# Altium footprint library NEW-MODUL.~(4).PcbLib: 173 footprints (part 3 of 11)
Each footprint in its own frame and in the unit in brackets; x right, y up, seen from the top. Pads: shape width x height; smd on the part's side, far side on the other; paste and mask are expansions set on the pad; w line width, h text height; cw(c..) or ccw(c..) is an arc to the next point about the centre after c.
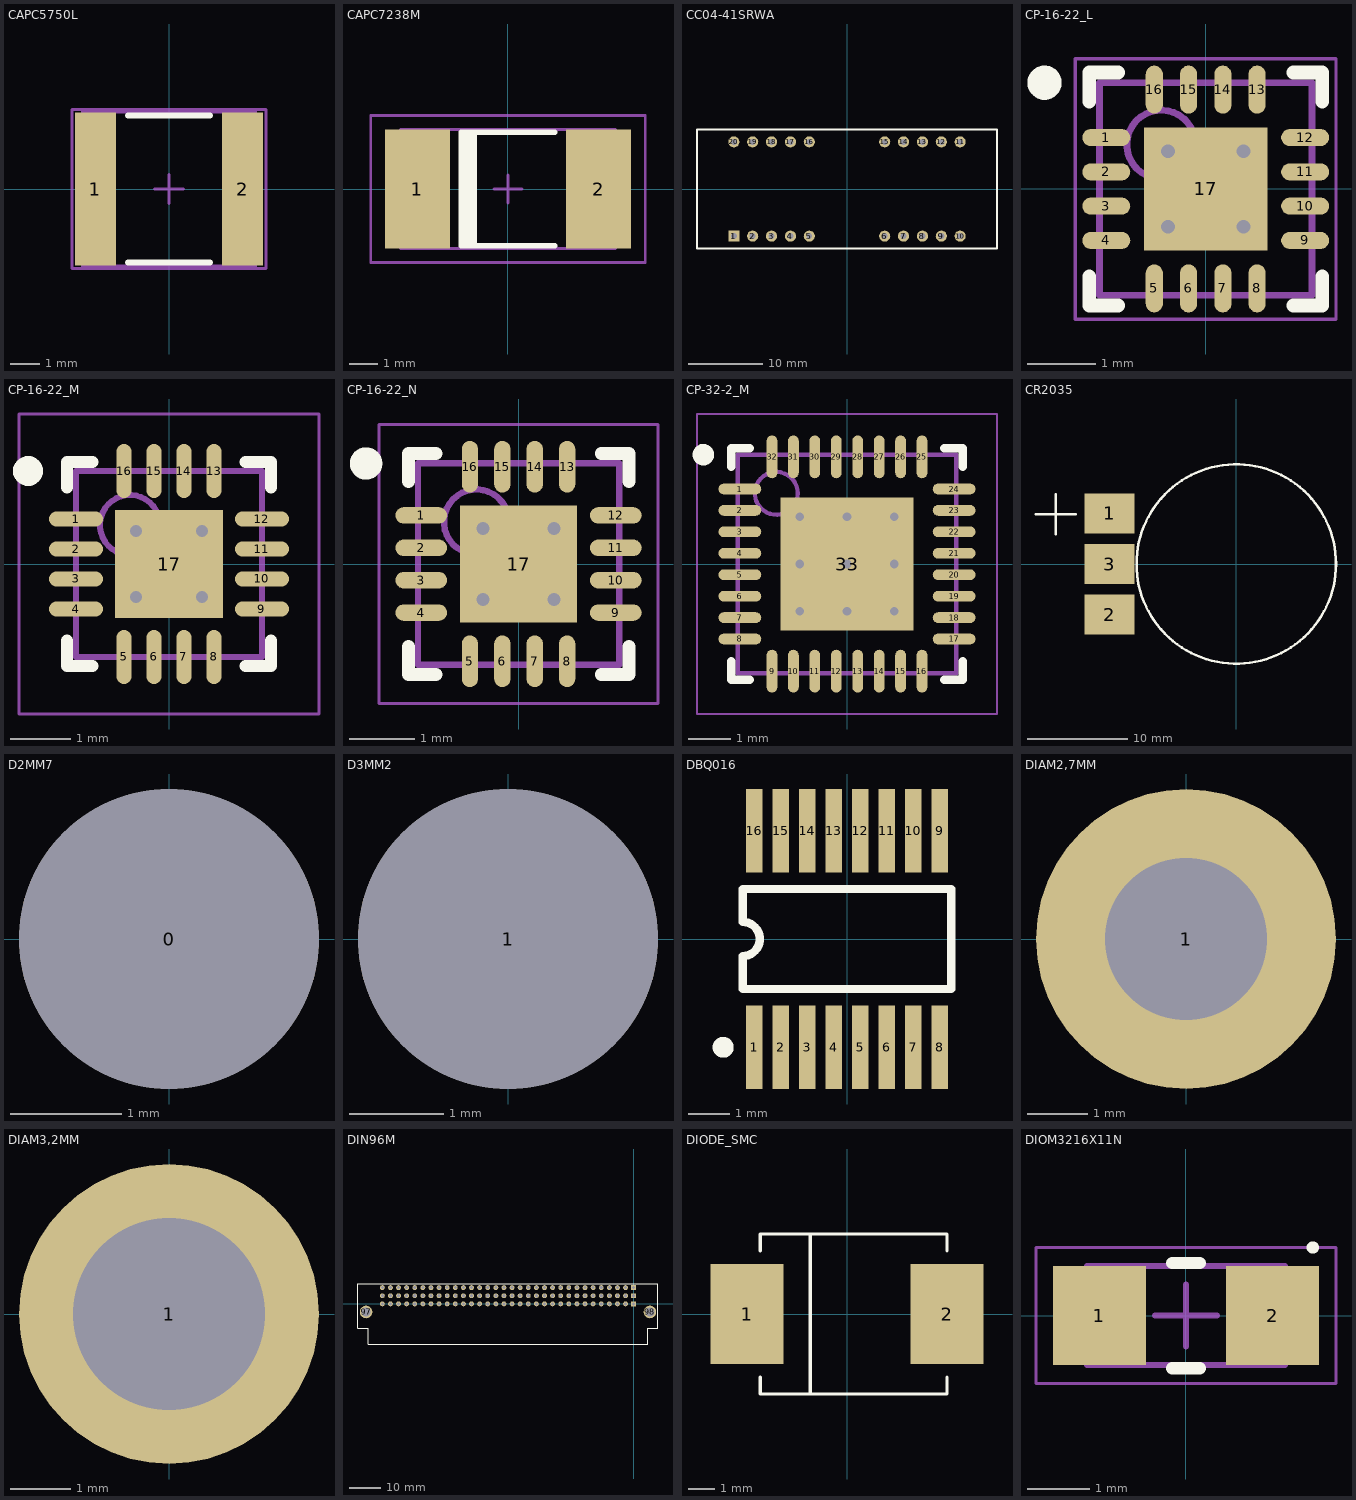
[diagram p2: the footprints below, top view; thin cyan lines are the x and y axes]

## CAPC5750L [mm] "Chip Capacitor, Body 5.7x5.0mm, IPC High Density"
height 1.35
pads (2):
  rect 1.4x5.2 smd: 1(-2.5,0) 2(2.5,0)
Top Overlay:
  lines w0.2: -1.4,-2.5 1.4,-2.5 ; -1.4,2.5 1.4,2.5
Mechanical 13:
  lines w0.1: -2.95,-2.625 2.95,-2.625 2.95,2.625 -2.95,2.625 -2.95,-2.625
Mechanical 15:
  lines w0.1: -0.5,0 0.5,0 ; 0,-0.5 0,0.5 ; -3.3,-2.7 3.3,-2.7 3.3,2.7 -3.3,2.7 -3.3,-2.7
3D body "User Library-CAPC5750X23.step": height 2.3, standoff 0, extent -2.85,-2.5 2.85,2.5

## CAPC7238M [mm] "Chip Capacitor, Body 7.2x3.8mm, IPC Low Density"
height 3.18
pads (2):
  rect 2.3x4.2 smd: 1(-3.2,0) 2(3.2,0)
Top Overlay:
  rectangle: -1.65,-2 -1.1,2
  lines w0.2: 1.65,-2 -1.65,-2 -1.65,2 1.65,2
Mechanical 13:
  lines w0.1: -3.8,-2.1 3.8,-2.1 3.8,2.1 -3.8,2.1 -3.8,-2.1
Mechanical 15:
  lines w0.1: -0.5,0 0.5,0 ; 0,-0.5 0,0.5 ; -4.85,-2.6 4.85,-2.6 4.85,2.6 -4.85,2.6 -4.85,-2.6
3D body "User Library-CAP_TANT_7343-31.step": height 3.1, standoff 0, extent -3.8,-2.3 3.8,2.3

## CC04-41SRWA [mm]
pads (20):
  rect 1.5x1.5 hole 0.8: 1(-15.24,-6.35)
  round 1.5 hole 0.8: 2(-12.7,-6.35) 3(-10.16,-6.35) 4(-7.62,-6.35) 5(-5.08,-6.35) 6(5.08,-6.35) 7(7.62,-6.35) 8(10.16,-6.35) 9(12.7,-6.35) 10(15.24,-6.35) 11(15.24,6.35) 12(12.7,6.35) 13(10.16,6.35) 14(7.62,6.35) 15(5.08,6.35) 16(-5.08,6.35) 17(-7.62,6.35) 18(-10.16,6.35) 19(-12.7,6.35) 20(-15.24,6.35)
Top Overlay:
  lines w0.254: -20.2,-8 -20.2,8 20.2,8 20.2,-8 -20.2,-8
3D body "end-el-san Co Ltd-King Bright CA04-41.step": height 7, standoff -4, extent -20.2,-8 20.2,8

## CP-16-22_L [mm] "QFN, 16-Leads, Body 3x3mm, Pitch 0.5mm, Thermal Pad 1.75x1.75mm, IPC High Density"
height 0.8
pads (17):
  oval 0.7x0.25 smd: 1(-1.45,0.75) 2(-1.45,0.25) 3(-1.45,-0.25) 4(-1.45,-0.75) 9(1.45,-0.75) 10(1.45,-0.25) 11(1.45,0.25) 12(1.45,0.75)
  oval 0.25x0.7 smd: 5(-0.75,-1.45) 6(-0.25,-1.45) 7(0.25,-1.45) 8(0.75,-1.45) 13(0.75,1.45) 14(0.25,1.45) 15(-0.25,1.45) 16(-0.75,1.45)
  rect 1.8x1.8 smd: 17(0,0)
via -0.55,0.55 diameter 0.5 hole 0.2
via 0.55,0.55 diameter 0.5 hole 0.2
via -0.55,-0.55 diameter 0.5 hole 0.2
via 0.55,-0.55 diameter 0.5 hole 0.2
Top Overlay:
  circle w0.25: c-2.35,1.55 r0.125
  lines w0.2: -1.7,-1.275 -1.7,-1.7 -1.275,-1.7 ; -1.7,1.275 -1.7,1.7 -1.275,1.7 ; 1.275,-1.7 1.7,-1.7 1.7,-1.275 ; 1.275,1.7 1.7,1.7 1.7,1.275
Mechanical 13:
  circle w0.1: c-0.65,0.65 r0.5
  lines w0.1: -1.55,-1.55 -1.55,1.55 1.55,1.55 1.55,-1.55 -1.55,-1.55
Mechanical 15:
  lines w0.05: -1.9,-1.9 -1.9,1.9 1.9,1.9 1.9,-1.9 -1.9,-1.9
  lines w0.1: -0.5,0 0.5,0 ; 0,-0.5 0,0.5
3D body: height 0.8, standoff 0, extent -1.55,-1.55 1.55,1.55

## CP-16-22_M [mm] "QFN, 16-Leads, Body 3x3mm, Pitch 0.5mm, Thermal Pad 1.75x1.75mm, IPC Low Density"
height 0.8
pads (17):
  oval 0.9x0.25 smd: 1(-1.55,0.75) 2(-1.55,0.25) 3(-1.55,-0.25) 4(-1.55,-0.75) 9(1.55,-0.75) 10(1.55,-0.25) 11(1.55,0.25) 12(1.55,0.75)
  oval 0.25x0.9 smd: 5(-0.75,-1.55) 6(-0.25,-1.55) 7(0.25,-1.55) 8(0.75,-1.55) 13(0.75,1.55) 14(0.25,1.55) 15(-0.25,1.55) 16(-0.75,1.55)
  rect 1.8x1.8 smd: 17(0,0)
via -0.55,0.55 diameter 0.5 hole 0.2
via 0.55,0.55 diameter 0.5 hole 0.2
via -0.55,-0.55 diameter 0.5 hole 0.2
via 0.55,-0.55 diameter 0.5 hole 0.2
Top Overlay:
  circle w0.25: c-2.35,1.55 r0.125
  lines w0.2: -1.7,-1.275 -1.7,-1.7 -1.275,-1.7 ; -1.7,1.275 -1.7,1.7 -1.275,1.7 ; 1.275,-1.7 1.7,-1.7 1.7,-1.275 ; 1.275,1.7 1.7,1.7 1.7,1.275
Mechanical 13:
  circle w0.1: c-0.65,0.65 r0.5
  lines w0.1: -1.55,-1.55 -1.55,1.55 1.55,1.55 1.55,-1.55 -1.55,-1.55
Mechanical 15:
  lines w0.05: -2.5,-2.5 -2.5,2.5 2.5,2.5 2.5,-2.5 -2.5,-2.5
  lines w0.1: -0.5,0 0.5,0 ; 0,-0.5 0,0.5
3D body "User Library-QFN-16.step": height 0.9, standoff 0, extent -1.501,-1.501 1.501,1.501

## CP-16-22_N [mm] "QFN, 16-Leads, Body 3x3mm, Pitch 0.5mm, Thermal Pad 1.75x1.75mm, IPC Medium Density"
height 0.8
pads (17):
  oval 0.8x0.25 smd: 1(-1.5,0.75) 2(-1.5,0.25) 3(-1.5,-0.25) 4(-1.5,-0.75) 9(1.5,-0.75) 10(1.5,-0.25) 11(1.5,0.25) 12(1.5,0.75)
  oval 0.25x0.8 smd: 5(-0.75,-1.5) 6(-0.25,-1.5) 7(0.25,-1.5) 8(0.75,-1.5) 13(0.75,1.5) 14(0.25,1.5) 15(-0.25,1.5) 16(-0.75,1.5)
  rect 1.8x1.8 smd: 17(0,0)
via -0.55,0.55 diameter 0.5 hole 0.2
via 0.55,0.55 diameter 0.5 hole 0.2
via -0.55,-0.55 diameter 0.5 hole 0.2
via 0.55,-0.55 diameter 0.5 hole 0.2
Top Overlay:
  circle w0.25: c-2.35,1.55 r0.125
  lines w0.2: -1.7,-1.275 -1.7,-1.7 -1.275,-1.7 ; -1.7,1.275 -1.7,1.7 -1.275,1.7 ; 1.275,-1.7 1.7,-1.7 1.7,-1.275 ; 1.275,1.7 1.7,1.7 1.7,1.275
Mechanical 13:
  circle w0.1: c-0.65,0.65 r0.5
  lines w0.1: -1.55,-1.55 -1.55,1.55 1.55,1.55 1.55,-1.55 -1.55,-1.55
Mechanical 15:
  lines w0.05: -2.15,-2.15 -2.15,2.15 2.15,2.15 2.15,-2.15 -2.15,-2.15
  lines w0.1: -0.5,0 0.5,0 ; 0,-0.5 0,0.5
3D body: height 0.8, standoff 0, extent -1.55,-1.55 1.55,1.55

## CP-32-2_M [mm] "QFN, 32-Leads, Body 5x5mm, Pitch 0.5mm, Thermal Pad 3.1x3.1mm, IPC Low Density"
height 1
pads (33):
  oval 1x0.25 smd: 1(-2.5,1.75) 2(-2.5,1.25) 3(-2.5,0.75) 4(-2.5,0.25) 5(-2.5,-0.25) 6(-2.5,-0.75) 7(-2.5,-1.25) 8(-2.5,-1.75) 17(2.5,-1.75) 18(2.5,-1.25) 19(2.5,-0.75) 20(2.5,-0.25) 21(2.5,0.25) 22(2.5,0.75) 23(2.5,1.25) 24(2.5,1.75)
  oval 0.25x1 smd: 9(-1.75,-2.5) 10(-1.25,-2.5) 11(-0.75,-2.5) 12(-0.25,-2.5) 13(0.25,-2.5) 14(0.75,-2.5) 15(1.25,-2.5) 16(1.75,-2.5) 25(1.75,2.5) 26(1.25,2.5) 27(0.75,2.5) 28(0.25,2.5) 29(-0.25,2.5) 30(-0.75,2.5) 31(-1.25,2.5) 32(-1.75,2.5)
  rect 3.1x3.1 smd: 33(0,0)
via -1.1,1.1 diameter 0.5 hole 0.2
via 0,1.1 diameter 0.5 hole 0.2
via 1.1,1.1 diameter 0.5 hole 0.2
via -1.1,0 diameter 0.5 hole 0.2
via 0,0 diameter 0.5 hole 0.2
via 1.1,0 diameter 0.5 hole 0.2
via -1.1,-1.1 diameter 0.5 hole 0.2
via 0,-1.1 diameter 0.5 hole 0.2
via 1.1,-1.1 diameter 0.5 hole 0.2
Top Overlay:
  circle w0.25: c-3.35,2.55 r0.125
  lines w0.2: -2.7,-2.275 -2.7,-2.7 -2.275,-2.7 ; -2.7,2.275 -2.7,2.7 -2.275,2.7 ; 2.275,-2.7 2.7,-2.7 2.7,-2.275 ; 2.275,2.7 2.7,2.7 2.7,2.275
Mechanical 13:
  circle w0.1: c-1.65,1.65 r0.5
  lines w0.1: -2.55,-2.55 -2.55,2.55 2.55,2.55 2.55,-2.55 -2.55,-2.55
Mechanical 15:
  lines w0.05: -3.5,-3.5 -3.5,3.5 3.5,3.5 3.5,-3.5 -3.5,-3.5
  lines w0.1: -0.5,0 0.5,0 ; 0,-0.5 0,0.5
3D body "User Library-LFCSP-32.step": height 0.89, standoff -0.04, extent -2.51,-2.51 2.51,2.51

## CR2035 [mm]
pads (3):
  rect 5x4 smd: 1(-12.7,5.08) 2(-12.7,-5.08) 3(-12.7,0)
Top Overlay:
  circle w0.254: c0,0 r10
  lines w0.254: -20.08,5 -16.08,5 ; -18.08,3 -18.08,7
3D body "User Library-cr2032.step": height 3.82, standoff 0.02, extent -15,-9.908 10.008,10.108

## D2MM7 [mm]
pads (1):
  round 2.7 hole 2.7 unplated: 0(0,0)

## D3MM2 [mm]
pads (1):
  round 3.2 hole 3.2 unplated: 1(0,0)

## DBQ016 [mm] "SSOP; 16 Leads; Body Width 3.9 mm; Pitch 0.635 mm"
height 1.76
pads (16):
  rect 0.4x2 smd: 1(-2.222,-2.6) 2(-1.587,-2.6) 3(-0.953,-2.6) 4(-0.318,-2.6) 5(0.318,-2.6) 6(0.953,-2.6) 7(1.587,-2.6) 8(2.222,-2.6) 9(2.222,2.6) 10(1.587,2.6) 11(0.953,2.6) 12(0.318,2.6) 13(-0.318,2.6) 14(-0.953,2.6) 15(-1.587,2.6) 16(-2.222,2.6)
Top Overlay:
  circle w0.25: c-2.973,-2.6 r0.125
  lines w0.2: -2.5,-1.2 -2.5,-0.408 ccw(c-2.5,0) -2.5,0.408 -2.5,1.2 2.5,1.2 2.5,-1.2 -2.5,-1.2
3D body "User Library-IPC SO(1).step": height 1.9, standoff 0, extent -2.5,-3.028 2.5,3.028

## DIAM2,7MM [mm]
pads (1):
  round 5 hole 2.7: 1(0,0)

## DIAM3,2MM [mm]
pads (1):
  round 5 hole 3.2: 1(0,0)

## DIN96M [mil]
pads (98):
  rect 60x60 hole 38: 1(0,0) 33(0,100) 65(0,200)
  round 60 hole 38: 2(-100,0) 3(-200,0) 4(-300,0) 5(-400,0) 6(-500,0) 7(-600,0) 8(-700,0) 9(-800,0) 10(-900,0) 11(-1000,0) 12(-1100,0) 13(-1200,0) 14(-1300,0) 15(-1400,0) 16(-1500,0) 17(-1600,0) 18(-1700,0) 19(-1800,0) 20(-1900,0) 21(-2000,0) 22(-2100,0) 23(-2200,0) 24(-2300,0) 25(-2400,0) 26(-2500,0) 27(-2600,0) 28(-2700,0) 29(-2800,0) 30(-2900,0) 31(-3000,0) 32(-3100,0) 34(-100,100) 35(-200,100) 36(-300,100) 37(-400,100) 38(-500,100) 39(-600,100) 40(-700,100) 41(-800,100) 42(-900,100) 43(-1000,100) 44(-1100,100) 45(-1200,100) 46(-1300,100) 47(-1400,100) 48(-1500,100) 49(-1600,100) 50(-1700,100) 51(-1800,100) 52(-1900,100) 53(-2000,100) 54(-2100,100) 55(-2200,100) 56(-2300,100) 57(-2400,100) 58(-2500,100) 59(-2600,100) 60(-2700,100) 61(-2800,100) 62(-2900,100) 63(-3000,100) 64(-3100,100) 66(-100,200) 67(-200,200) 68(-300,200) 69(-400,200) 70(-500,200) 71(-600,200) 72(-700,200) 73(-800,200) 74(-900,200) 75(-1000,200) 76(-1100,200) 77(-1200,200) 78(-1300,200) 79(-1400,200) 80(-1500,200) 81(-1600,200) 82(-1700,200) 83(-1800,200) 84(-1900,200) 85(-2000,200) 86(-2100,200) 87(-2200,200) 88(-2300,200) 89(-2400,200) 90(-2500,200) 91(-2600,200) 92(-2700,200) 93(-2800,200) 94(-2900,200) 95(-3000,200) 96(-3100,200)
  round 156 hole 110: 97(-3300,-100) 98(200,-100)
Top Overlay:
  lines w10: -3400,-300 -3275,-300 -3275,-500 175,-500 175,-300 300,-300 300,250 -3400,250 -3400,-300
3D body "connector_a-cm96abcr.stp": height 376.58, standoff -117.51, extent -3400.39,-500 300.39,213

## DIODE_SMC [mil]
pads (2):
  rect 110x150 smd: 1(-150,0) 2(150,0)
Top Overlay:
  lines w5: -130,-95 -130,-120 150,-120 150,-95 ; -130,95 -130,120 150,120 150,95 ; -55,-120 -55,120
Mechanical 1:
  lines w1: -130,-120 150,-120 ; -130,120 150,120
3D body "User Library-Diode Molded Body.step": height 85.64, standoff 0.6, extent -155.51,-118.11 155.51,118.11

## DIOM3216X11N [mm] "Molded Diode, 2-Leads, Body 3,20x1,60mm, IPC Medium Density"
height 1.1
pads (2):
  rect 1.5x1.6 smd: 1(-1.4,0) 2(1.4,0)
Top Overlay:
  circle w0.1: c2.05,1.1 r0.05
  lines w0.2: -0.225,-0.85 0.225,-0.85 ; -0.225,0.85 0.225,0.85
Mechanical 13:
  rectangle: 1.17,-0.8 1.6,0.8
  lines w0.1: -1.6,-0.8 1.6,-0.8 1.6,0.8 -1.6,0.8 -1.6,-0.8
Mechanical 15:
  lines w0.05: -2.425,-1.1 2.425,-1.1 2.425,1.1 -2.425,1.1 -2.425,-1.1
  lines w0.1: -0.5,0 0.5,0 ; 0,-0.5 0,0.5
3D body "User Library-LED 1206 top R.step": height 0.7, standoff 0.19, extent -1,-0.8 1,0.8
3D body "User Library-LED 1206 btm.step": height 0.58, standoff 0, extent -1.6,-0.8 1.6,0.8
